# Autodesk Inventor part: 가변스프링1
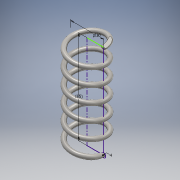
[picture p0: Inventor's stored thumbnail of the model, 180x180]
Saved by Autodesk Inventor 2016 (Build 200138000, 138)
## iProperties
Created: 2017-03
Part Number: 가변스프링1
Material: 강철, 탄소
Document SubType Name: Modeling
Designer: USER
Mass: 55.2263 g
Surface Area: 71.3407 cm^2
Volume: 7.0352 cm^3
Density: 7.85 g/cm^3
Appearance: 반연마
Author: USER
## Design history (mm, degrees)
sketch "스케치1"
  geometry: L1 (0, 0)-(-15, 0); L2 (-15, 0)-(-15, 84.368); L3 (-15, 84.368)-(0, 84.368); L4 (0, 84.368)-(0, 0); C1 r 2 at (-15, 0)
  constraints: 8 end point, 2 parallel, 1 centre point, 1 coincident, 1 horizontal, 1 perpendicular
  dimensions: "d0" = 4 diameter of C1; "d1" = 30 diameter of L2 L4; "d2" = 84.36759 distance between parallel lines of L1 L3 (derived)
feature "코일1" pitch "d3" = 10; turns "d5" = 6; dims "d4" = 84.36759 (= d2), "d6" = 0, angle "d7" = 90 deg, angle "d8" = 90 deg, "d9" = 0, "d10" = 0
sketch "스케치2"
  geometry: L1 (13, 0)-(17, 0) reference; 1 further point
  constraints: 1 horizontal alignment
extrude "돌출1" cut sketch "스케치2" stored distance "d11" = 10; taper "d12" = 0 deg
node "작업 평면1"
sketch "스케치3"
  geometry: L1 (-13, 0)-(-17, 0) reference; 1 further point
  constraints: 1 horizontal alignment
extrude "돌출2" cut sketch "스케치3" stored distance "d13" = 10; taper "d14" = 0 deg
node "솔리드1"
node "절단 모서리 투영1"
node "절단 모서리 투영2"
